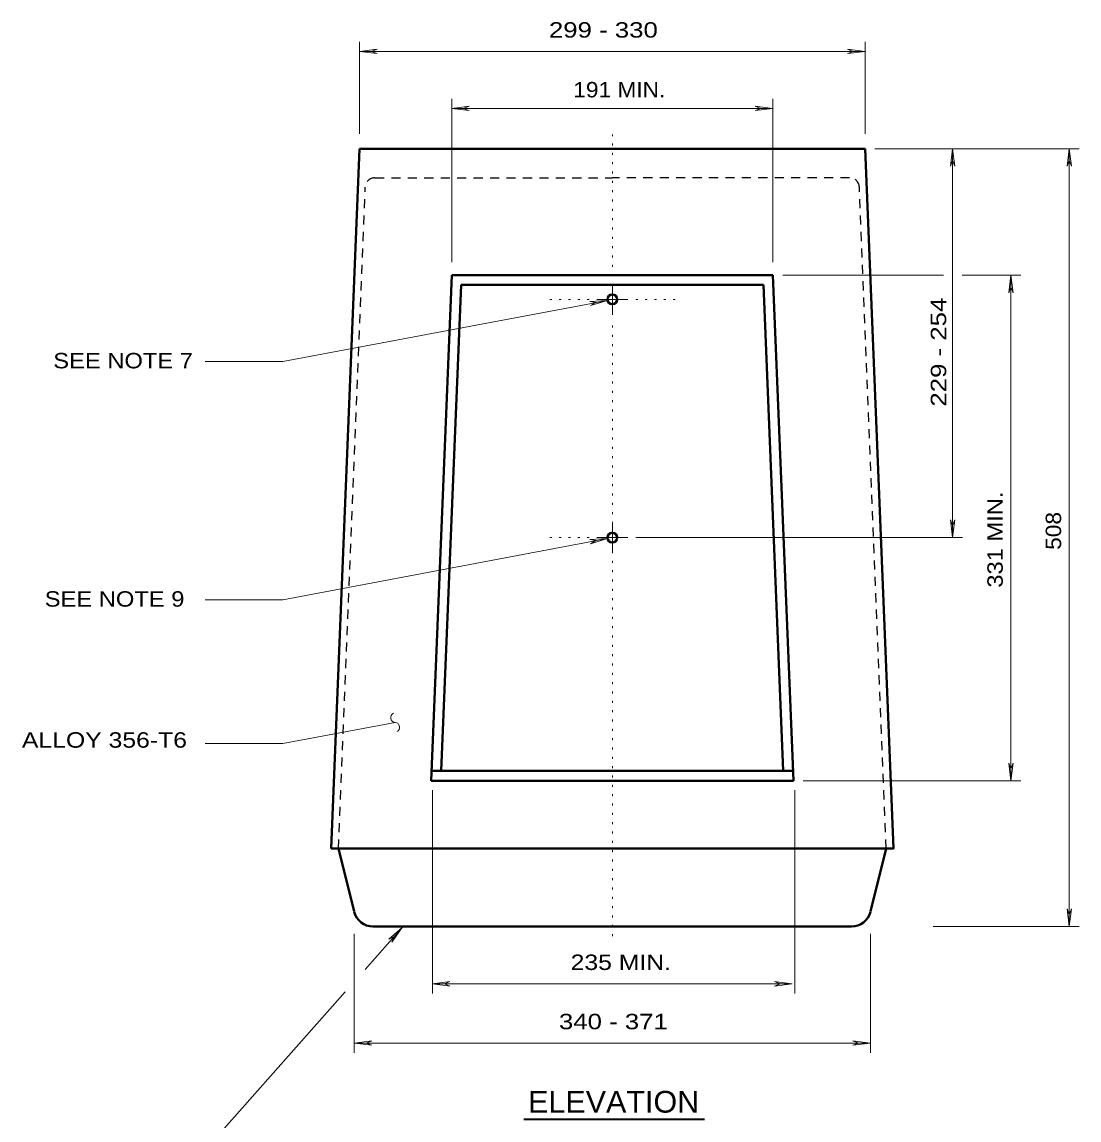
# Model space of a CAD drawing. Extents: x 312583 to 312854, y 144419 to 144597.
# Drawn here: x 312690 to 312742.1, y 144475.1 to 144529.2 of the extents above; entities that cross this region are included whole.
import ezdxf
from ezdxf.enums import TextEntityAlignment as Align

# ---------------------------------------------------------------- set-up
doc = ezdxf.new("R2010")
doc.units = 0
doc.header["$LTSCALE"] = 0.3
doc.linetypes.add('DOTTED', pattern=[1.5, 0.3, -1.2])
doc.linetypes.add('SHORT_DASHED', pattern=[2.7, 1.5, -1.2])
doc.layers.add('1', color=7, linetype='Continuous', lineweight=40)
doc.layers.add('2', color=7, linetype='Continuous', lineweight=13)

msp = doc.modelspace()

# ---------------------------------------------------------------- linework, layer by layer
at = {"layer": '1'}
for p, q in [((312705.1927, 144488.4263), (312706.5957, 144522.9263)), ((312719.054, 144522.9263), (312706.5957, 144522.9263)), ((312719.054, 144522.9263), (312731.5123, 144522.9263)), ((312710.1223, 144491.7766), (312711.1343, 144516.6933)), ((312719.054, 144516.6933), (312711.1343, 144516.6933)), ((312719.054, 144516.6933), (312726.966, 144516.6933)), ((312727.978, 144491.7766), (312726.966, 144516.6933)), ((312710.6207, 144492.2596), (312711.5943, 144516.2179)), ((312719.054, 144516.2179), (312711.5943, 144516.2179)), ((312719.054, 144516.2179), (312726.506, 144516.2179)), ((312727.4797, 144492.2596), (312726.506, 144516.2179)), ((312719.054, 144492.2596), (312710.1453, 144492.2596)), ((312719.054, 144492.2596), (312727.9627, 144492.2596)), ((312719.054, 144491.7766), (312710.1223, 144491.7766)), ((312719.054, 144491.7766), (312727.978, 144491.7766)), ((312705.553, 144488.4263), (312706.3273, 144485.3213)), ((312732.555, 144488.4263), (312731.773, 144485.3213)), ((312707.255, 144484.5929), (312719.054, 144484.5929)), ((312730.8453, 144484.5929), (312719.054, 144484.5929))]:
    msp.add_line(p, q, dxfattribs=at)
at = {"layer": '1', "linetype": 'SHORT_DASHED', "lineweight": 25}
for p, q in [((312707.3547, 144521.4849), (312719.054, 144521.4849)), ((312730.7457, 144521.4849), (312719.054, 144521.4849)), ((312705.553, 144488.4263), (312706.8717, 144521.0249)), ((312732.555, 144488.4263), (312731.2287, 144521.0249))]:
    msp.add_line(p, q, dxfattribs=at)
at = {"layer": '1'}
msp.add_lwpolyline([(312705.1927, 144488.4263), (312732.9077, 144488.4263), (312731.5123, 144522.9263)], dxfattribs=at)
for centre in [(312719.0502, 144515.4973), (312719.0502, 144515.4973), (312719.0502, 144503.7577), (312719.0502, 144503.7577)]:
    msp.add_circle(centre, 0.2396, dxfattribs=at)
at = {"layer": '1', "linetype": 'SHORT_DASHED', "lineweight": 25}
for centre, start, end in [((312707.3526, 144521.0077), 90, 177.67414), ((312730.7477, 144521.0077), 2.32586, 90)]:
    msp.add_arc(centre, 0.4792, start, end, dxfattribs=at)
at = {"layer": '1'}
for centre, start, end in [((312707.2562, 144485.5493), 194.04369, 270), ((312730.8442, 144485.5493), 270, 345.95631)]:
    msp.add_arc(centre, 0.9583, start, end, dxfattribs=at)
at = {"layer": '2'}
for p, q in [((312706.5957, 144523.6546), (312706.5957, 144528.1933)), ((312731.5123, 144523.6546), (312731.5123, 144528.1933)), ((312706.5957, 144527.7179), (312707.462, 144527.8253)), ((312706.5957, 144527.7179), (312731.5123, 144527.7179)), ((312706.5957, 144527.7179), (312707.462, 144527.6106)), ((312707.462, 144527.8253), (312707.186, 144527.7179)), ((312707.462, 144527.6106), (312707.186, 144527.7179)), ((312730.646, 144527.8253), (312730.922, 144527.7179)), ((312731.5123, 144527.7179), (312730.646, 144527.8253)), ((312730.646, 144527.6106), (312730.922, 144527.7179)), ((312731.5123, 144527.7179), (312730.646, 144527.6106)), ((312711.1343, 144517.3296), (312711.1343, 144525.3873)), ((312726.966, 144517.3296), (312726.966, 144525.3873)), ((312711.1343, 144524.9119), (312712.0007, 144525.0193)), ((312711.1343, 144524.9119), (312726.966, 144524.9119)), ((312711.1343, 144524.9119), (312712.0007, 144524.8046)), ((312712.0007, 144525.0193), (312711.7247, 144524.9119)), ((312712.0007, 144524.8046), (312711.7247, 144524.9119)), ((312726.0997, 144525.0193), (312726.3757, 144524.9119)), ((312726.966, 144524.9119), (312726.0997, 144525.0193)), ((312726.0997, 144524.8046), (312726.3757, 144524.9119)), ((312726.966, 144524.9119), (312726.0997, 144524.8046)), ((312731.9877, 144522.9263), (312742.054, 144522.9263)), ((312735.821, 144522.9263), (312735.7137, 144522.0599)), ((312735.821, 144503.7596), (312735.821, 144522.9263)), ((312735.821, 144522.9263), (312735.9283, 144522.0599)), ((312741.571, 144522.9263), (312741.4637, 144522.0599)), ((312741.571, 144484.5929), (312741.571, 144522.9263)), ((312741.571, 144522.9263), (312741.6783, 144522.0599)), ((312735.7137, 144522.0599), (312735.821, 144522.3359)), ((312735.9283, 144522.0599), (312735.821, 144522.3359)), ((312741.4637, 144522.0599), (312741.571, 144522.3359)), ((312741.6783, 144522.0599), (312741.571, 144522.3359)), ((312727.449, 144516.6933), (312735.3763, 144516.6933)), ((312736.2887, 144516.6933), (312739.179, 144516.6933)), ((312738.696, 144516.6933), (312738.5887, 144515.8269)), ((312738.696, 144491.7766), (312738.696, 144516.6933)), ((312738.696, 144516.6933), (312738.8033, 144515.8269)), ((312719.054, 144515.4973), (312719.054, 144516.2639)), ((312719.054, 144515.4973), (312719.054, 144516.2639)), ((312738.5887, 144515.8269), (312738.696, 144516.1029)), ((312738.8033, 144515.8269), (312738.696, 144516.1029)), ((312718.8163, 144515.4513), (312702.816, 144512.4383)), ((312718.8163, 144515.4513), (312717.9423, 144515.3976)), ((312718.8163, 144515.4513), (312717.9807, 144515.1906)), ((312719.054, 144515.4973), (312718.2873, 144515.4973)), ((312719.054, 144515.4973), (312719.8207, 144515.4973)), ((312719.054, 144515.4973), (312719.054, 144514.7306)), ((312717.9423, 144515.3976), (312718.2337, 144515.3439)), ((312717.9807, 144515.1906), (312718.2337, 144515.3439)), ((312702.816, 144512.4383), (312698.9827, 144512.4383)), ((312735.7137, 144504.6259), (312735.821, 144504.3499)), ((312735.821, 144503.7596), (312735.7137, 144504.6259)), ((312735.9283, 144504.6259), (312735.821, 144504.3499)), ((312735.821, 144503.7596), (312735.9283, 144504.6259)), ((312719.054, 144503.7596), (312719.054, 144504.5263)), ((312719.054, 144503.7596), (312719.054, 144504.5263)), ((312718.8163, 144503.7136), (312702.816, 144500.6929)), ((312718.8163, 144503.7136), (312717.9423, 144503.6599)), ((312717.9423, 144503.6599), (312718.2337, 144503.6063)), ((312718.8163, 144503.7136), (312717.9807, 144503.4453)), ((312717.9807, 144503.4453), (312718.2337, 144503.6063)), ((312719.054, 144503.7596), (312718.2873, 144503.7596)), ((312719.054, 144503.7596), (312719.054, 144502.9929)), ((312719.054, 144503.7596), (312719.8207, 144503.7596)), ((312720.204, 144503.7596), (312736.304, 144503.7596)), ((312702.816, 144500.6929), (312698.9827, 144500.6929)), ((312738.5887, 144492.6429), (312738.696, 144492.3669)), ((312738.696, 144491.7766), (312738.5887, 144492.6429)), ((312738.8033, 144492.6429), (312738.696, 144492.3669)), ((312738.696, 144491.7766), (312738.8033, 144492.6429)), ((312728.461, 144491.7766), (312739.179, 144491.7766)), ((312710.1837, 144491.3013), (312710.1837, 144481.2886)), ((312728.0393, 144491.3013), (312728.0393, 144481.2886)), ((312741.4637, 144485.4593), (312741.571, 144485.1833)), ((312741.571, 144484.5929), (312741.4637, 144485.4593)), ((312741.6783, 144485.4593), (312741.571, 144485.1833)), ((312741.571, 144484.5929), (312741.6783, 144485.4593)), ((312734.8627, 144484.5929), (312742.054, 144484.5929)), ((312706.335, 144478.3599), (312706.335, 144484.2249)), ((312706.864, 144482.4769), (312708.6887, 144484.5393)), ((312708.6887, 144484.5393), (312708.037, 144483.9643)), ((312708.037, 144483.9643), (312708.2977, 144484.0946)), ((312708.6887, 144484.5393), (312708.1903, 144483.8186)), ((312708.1903, 144483.8186), (312708.2977, 144484.0946)), ((312731.773, 144478.3599), (312731.773, 144484.2249)), ((312710.1837, 144481.7639), (312711.05, 144481.8713)), ((312711.05, 144481.8713), (312710.774, 144481.7639)), ((312727.0503, 144481.8713), (312727.3263, 144481.7639)), ((312727.9167, 144481.7639), (312727.0503, 144481.8713)), ((312699.4043, 144474.0513), (312705.8827, 144481.3729)), ((312710.1837, 144481.7639), (312727.9167, 144481.7639)), ((312710.1837, 144481.7639), (312711.05, 144481.6566)), ((312711.05, 144481.6566), (312710.774, 144481.7639)), ((312727.0503, 144481.6566), (312727.3263, 144481.7639)), ((312727.9167, 144481.7639), (312727.0503, 144481.6566)), ((312706.335, 144478.8429), (312707.2013, 144478.9503)), ((312706.335, 144478.8429), (312719.054, 144478.8429)), ((312706.335, 144478.8429), (312707.2013, 144478.7356)), ((312707.2013, 144478.9503), (312706.9253, 144478.8429)), ((312707.2013, 144478.7356), (312706.9253, 144478.8429)), ((312731.773, 144478.8429), (312719.054, 144478.8429)), ((312730.9067, 144478.9503), (312731.1827, 144478.8429)), ((312731.773, 144478.8429), (312730.9067, 144478.9503)), ((312730.9067, 144478.7356), (312731.1827, 144478.8429)), ((312731.773, 144478.8429), (312730.9067, 144478.7356))]:
    msp.add_line(p, q, dxfattribs=at)
at = {"layer": '2', "linetype": 'DOTTED'}
for p, q in [((312719.054, 144516.6473), (312719.054, 144523.6239)), ((312717.904, 144515.4973), (312715.627, 144515.4973)), ((312720.204, 144515.4973), (312722.1513, 144515.4973)), ((312719.054, 144504.9096), (312719.054, 144514.4316)), ((312717.904, 144503.7596), (312715.627, 144503.7596)), ((312719.054, 144502.6096), (312719.054, 144483.7726))]:
    msp.add_line(p, q, dxfattribs=at)
at = {"layer": '2', "lineweight": 35}
msp.add_line((312714.6961, 144475.0939), (312723.5942, 144475.0939), dxfattribs=at)
at = {"layer": '2'}
msp.add_lwpolyline([(312708.3513, 144494.6516), (312702.816, 144493.6013), (312698.9827, 144493.6013)], dxfattribs=at)
for centre, start, end in [((312708.3655, 144494.8866), 115.69034, 265.69034), ((312708.3295, 144494.409), 295.69034, 85.69034)]:
    msp.add_arc(centre, 0.2395, start, end, dxfattribs=at)

# ---------------------------------------------------------------- texts
for s, width, p in [('299 - 330 ', 1.25, (312715.9267, 144528.4002)), ('191 MIN.', 1.1, (312717.1278, 144525.4539)), ('SEE NOTE 7', 1.15, (312691.4989, 144512.0993)), ('SEE NOTE 9', 1.15, (312691.0781, 144500.3539)), ('ALLOY 356-T6', 1.2, (312689.9535, 144493.4026)), ('235 MIN.', 1.2, (312716.9972, 144482.4462)), ('340 - 371 ', 1.25, (312716.4199, 144479.5252))]:
    msp.add_text(s, height=0.76, dxfattribs=dict(at, width=width)).set_placement(p)
for s, width, p in [('229 - 254', 1.25, (312735.5068, 144510.2134)), ('331 MIN.', 1.15, (312738.2954, 144501.2889)), ('508', 1.1, (312741.1704, 144503.1547))]:
    msp.add_text(s, height=0.76, rotation=90, dxfattribs=dict(at, width=width)).set_placement(p)
at = {"layer": '2', "width": 1.05}
msp.add_text('ELEVATION', height=1.07, dxfattribs=at).set_placement((312719.1176, 144475.4157), align=Align.CENTER)

doc.saveas('drawing.dxf')
